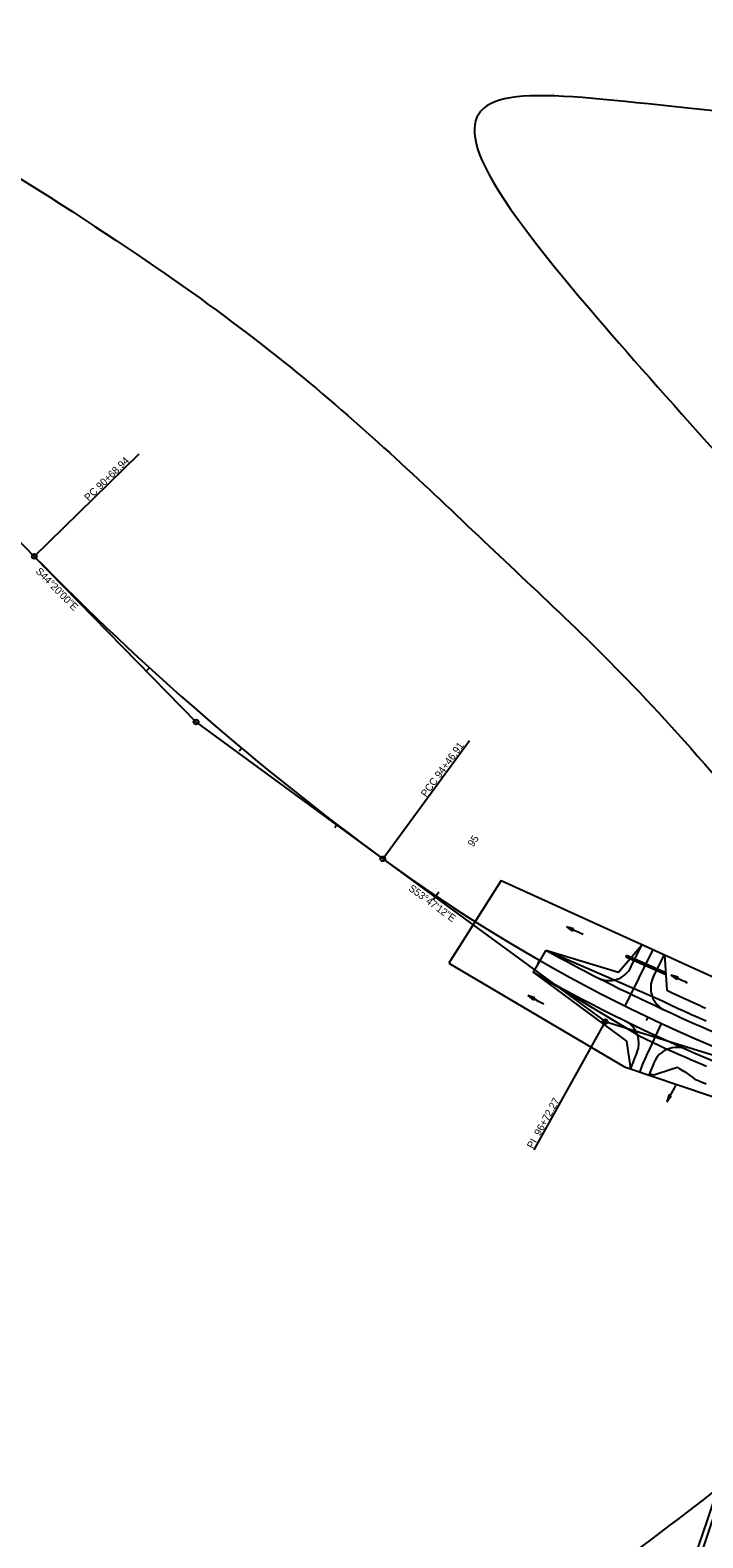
# Model space of a CAD drawing. Extents: x 1 to 1477871, y 1 to 1872901.
# Drawn here: x 1442950 to 1443501, y 1854698 to 1855932 of the extents above; entities that cross this region are included whole.
import ezdxf

# ---------------------------------------------------------------- set-up
doc = ezdxf.new("R2010")
doc.units = 0
for name, color, linetype in [('R_Drive', 7, 'Continuous'), ('R_Floodplain', 7, 'Continuous'), ('R_Horz Alg', 7, 'Continuous'), ('R_Horz Alg Annot', 7, 'Continuous'), ('R_No Plot', 7, 'Continuous'), ('R_Proposed Const Limits_Cut', 7, 'Continuous'), ('R_Proposed Const Limits_Fill', 7, 'Continuous'), ('R_Proposed Road_Lane', 7, 'Continuous'), ('R_Proposed Road_Shoulder', 7, 'Continuous'), ('R_ROW', 7, 'Continuous'), ('R_Water', 7, 'Continuous')]:
    doc.layers.add(name, color=color, linetype=linetype)

msp = doc.modelspace()

# ---------------------------------------------------------------- linework, layer by layer
at = {"layer": 'R_Drive'}
for p, q in [((1443441.9, 1855165.4), (1443451, 1855183.7)), ((1443451, 1855183.7), (1443469.2, 1855175.4)), ((1443460.1, 1855157.1), (1443469.2, 1855175.4)), ((1443441.5, 1855082), (1443456.7, 1855076.9))]:
    msp.add_line(p, q, dxfattribs=at)
for centre, radius, start, end in [((1443424, 1855174.3), 20, 243.049, 333.6597), ((1443478, 1855148.2), 20, 153.6597, 244.9648), ((1443428.4, 1855103.2), 20, 336.3358, 63.8895), ((1443637.2, 1855011.7), 208, 156.3358, 160.2285), ((1443479.2, 1855079.6), 20, 66.2169, 156.7535), ((1443637.2, 1855011.7), 192, 156.7535, 160.1367)]:
    msp.add_arc(centre, radius, start, end, dxfattribs=at)
at = {"layer": 'R_Floodplain'}
for points in [[(1444534.2, 1857777.8), (1444398.8, 1857609.1), (1444367.9, 1857131.5), (1444306.1, 1856808.3), (1444135, 1856378.3), (1444024.6, 1856227.9), (1443837.9, 1855964.8), (1443664.5, 1855852.1), (1443479, 1855867.8), (1443336, 1855886), (1443298.4, 1855854.5), (1443356.6, 1855756.3), (1443606.5, 1855482.3), (1443757.2, 1855307.3), (1443863.1, 1855113.6), (1443878.6, 1855007.9), (1443849.9, 1854910.1), (1443760.7, 1854753.1), (1443429.3, 1854512), (1443240.9, 1854371.2), (1443115.3, 1854254), (1443060.9, 1853889.1), (1443100, 1853680.3), (1443032.1, 1853386.7), (1443001.5, 1853198.3), (1444534.2, 1857777.8), (1443001.5, 1853198.3)], [(1442151.1, 1856970.7), (1442271.2, 1856854.3), (1442333, 1856625.2), (1442433.6, 1856208.1), (1442553.7, 1856042), (1442997.4, 1855782.6), (1443193.8, 1855637.1), (1443334.5, 1855500.1), (1443473.9, 1855372.8), (1443683.7, 1855109.7), (1443730.1, 1855020.6), (1443721.3, 1854972.2), (1443705.7, 1854932.6), (1443621.8, 1854821.7), (1443387.2, 1854639.6), (1443131.3, 1854479.5), (1443010.1, 1854397.1), (1442954.3, 1854286.7), (1442894.9, 1853873.3), (1442881.6, 1853521.7), (1442881.6, 1853348.3), (1442151.1, 1856970.7), (1442881.6, 1853348.3)]]:
    msp.add_open_spline(points, degree=3, dxfattribs=at)
at = {"layer": 'R_Horz Alg'}
msp.add_line((1442739.1, 1855720.9), (1442953.7, 1855501.3), dxfattribs=at)
for centre, radius, start, end in [((1444592.3, 1857102.2), 2290.8, 224.3333, 233.7866), ((1444035.4, 1856341.6), 1348.1, 233.7866, 252.7667), ((1444035.4, 1856341.6), 1348.1, 233.7866, 252.7667)]:
    msp.add_arc(centre, radius, start, end, dxfattribs=at)
at = {"layer": 'R_Horz Alg Annot'}
for p, q in [((1442953.7, 1855501.3), (1443086.1, 1855365.8)), ((1443086.1, 1855365.8), (1443238.9, 1855253.9)), ((1443238.9, 1855253.9), (1443420.7, 1855120.7)), ((1443238.9, 1855253.9), (1443420.7, 1855120.7)), ((1443420.7, 1855120.7), (1443636, 1855054))]:
    msp.add_line(p, q, dxfattribs=at)
for points in [[(1442953.7, 1855501.3), (1443039.6, 1855585.1)], [(1443045.9, 1855408), (1443047.9, 1855410.2)], [(1443238.9, 1855253.9), (1443309.8, 1855350.7)], [(1443121.3, 1855342.1), (1443123.2, 1855344.4)], [(1443199.5, 1855279.6), (1443201.3, 1855282)], [(1443284.6, 1855226.7), (1443280.1, 1855220)], [(1443365.8, 1855168), (1443367.3, 1855170.6)], [(1443420.7, 1855120.7), (1443362.5, 1855015.8)], [(1443454.6, 1855121.6), (1443455.9, 1855124.3)]]:
    msp.add_lwpolyline(points, dxfattribs=at)
for centre in [(1442953.7, 1855501.3), (1443086.1, 1855365.8), (1443238.9, 1855253.9), (1443420.7, 1855120.7)]:
    msp.add_circle(centre, 2, dxfattribs=at)
at = {"layer": 'R_No Plot'}
for p, q in [((1443372.2, 1855179.1), (1443361.8, 1855161.1)), ((1443437.2, 1855133.4), (1443460.1, 1855179.6)), ((1443466.7, 1855119.2), (1443455.9, 1855096))]:
    msp.add_line(p, q, dxfattribs=at)
msp.add_arc((1443637.2, 1855011.7), 200, 155.0504, 160.1844, dxfattribs=at)
at = {"layer": 'R_Proposed Const Limits_Cut'}
for points in [[(1443372.2, 1855179.1), (1443431.6, 1855161.3), (1443451, 1855183.7), (1443469.2, 1855175.4), (1443471.1, 1855146.4)], [(1443361.8, 1855161.1), (1443438.2, 1855104.6), (1443441.5, 1855082), (1443456.7, 1855076.9), (1443458.6, 1855077.6), (1443460.6, 1855077.3), (1443475.5, 1855082.2), (1443478.2, 1855082.9), (1443479.6, 1855083.5)]]:
    msp.add_lwpolyline(points, dxfattribs=at)
at = {"layer": 'R_Proposed Const Limits_Fill'}
for points in [[(1443471.1, 1855146.4), (1443471.8, 1855146.2), (1443473.9, 1855145.1), (1443476.1, 1855144), (1443480.5, 1855142.1), (1443480.6, 1855142), (1443485.1, 1855140), (1443487.1, 1855139), (1443489.5, 1855137.9), (1443493.7, 1855136), (1443494, 1855135.8), (1443498.4, 1855133.8), (1443500.4, 1855132.9), (1443502.9, 1855131.8)], [(1443479.6, 1855083.5), (1443481.2, 1855082.4), (1443485.3, 1855080), (1443485.6, 1855079.8), (1443489.8, 1855076.8), (1443491.6, 1855075.5), (1443494.1, 1855073.7), (1443498.3, 1855071.9), (1443498.8, 1855071.7), (1443503.5, 1855069.8)]]:
    msp.add_lwpolyline(points, dxfattribs=at)
at = {"layer": 'R_Proposed Road_Lane'}
for centre, radius, start, end in [((1444020.9, 1856348.4), 1337.1, 240.9749, 245.227), ((1444035.4, 1856341.6), 1359.1, 240.293, 252.7667), ((1444035.4, 1856341.6), 1337.1, 244.5429, 252.7667)]:
    msp.add_arc(centre, radius, start, end, dxfattribs=at)
at = {"layer": 'R_Proposed Road_Shoulder'}
for p, q in [((1443372.2, 1855179.1), (1443463.2, 1855139.7)), ((1443448.6, 1855109), (1443361.8, 1855161.1))]:
    msp.add_line(p, q, dxfattribs=at)
for points in [[(1443463.2, 1855139.7), (1443467.7, 1855137.6), (1443469.8, 1855136.5), (1443472.1, 1855135.5), (1443476.5, 1855133.4), (1443476.6, 1855133.4), (1443481.1, 1855131.3), (1443483.2, 1855130.4), (1443485.6, 1855129.3), (1443489.9, 1855127.3), (1443490.1, 1855127.2), (1443494.6, 1855125.2), (1443496.6, 1855124.4), (1443499.1, 1855123.2), (1443503.3, 1855121.4)], [(1443448.6, 1855109), (1443453.2, 1855106.8), (1443455.4, 1855105.8), (1443457.8, 1855104.7), (1443462.2, 1855102.6), (1443462.4, 1855102.5), (1443466.9, 1855100.4), (1443469.1, 1855099.4), (1443471.6, 1855098.3), (1443475.9, 1855096.3), (1443476.2, 1855096.2), (1443480.8, 1855094.2), (1443482.8, 1855093.3), (1443485.4, 1855092.1), (1443489.7, 1855090.2), (1443490.1, 1855090.1), (1443494.7, 1855088.1), (1443496.6, 1855087.2), (1443499.4, 1855086.1), (1443503.6, 1855084.3)]]:
    msp.add_lwpolyline(points, dxfattribs=at)
at = {"layer": 'R_ROW'}
for p, q in [((1443335.8, 1855236.2), (1443293, 1855168.6)), ((1443335.8, 1855236.2), (1443565.8, 1855131.3)), ((1443293, 1855168.6), (1443436.6, 1855083.7)), ((1443436.6, 1855083.7), (1443895.3, 1854928.7))]:
    msp.add_line(p, q, dxfattribs=at)
at = {"layer": 'R_Water'}
for p, q in [((1443389.1, 1855198.3), (1443394.1, 1855194.8)), ((1443394.9, 1855196.7), (1443389.1, 1855198.3)), ((1443394.1, 1855194.8), (1443394.9, 1855196.7)), ((1443438.2, 1855175.1), (1443437.6, 1855173.7)), ((1443438.2, 1855175.1), (1443470.5, 1855160.9)), ((1443437.6, 1855173.7), (1443469.9, 1855159.6)), ((1443469.9, 1855159.6), (1443470.5, 1855160.9)), ((1443474.5, 1855158.6), (1443479.5, 1855155.1)), ((1443480.4, 1855157.1), (1443474.5, 1855158.6)), ((1443479.5, 1855155.1), (1443480.4, 1855157.1)), ((1443357.4, 1855142.1), (1443362.1, 1855138.3)), ((1443363.1, 1855140.2), (1443357.4, 1855142.1)), ((1443362.1, 1855138.3), (1443363.1, 1855140.2)), ((1443473.1, 1855061), (1443471.1, 1855055.2)), ((1443471.1, 1855055.2), (1443474.9, 1855060)), ((1443474.9, 1855060), (1443473.1, 1855061))]:
    msp.add_line(p, q, dxfattribs=at)
for points in [[(1443402.7, 1855191.9), (1443400.4, 1855193), (1443398.7, 1855193.8), (1443395.9, 1855195.1), (1443391.3, 1855197.2), (1443389.1, 1855198.3)], [(1443488.1, 1855152.3), (1443485.9, 1855153.4), (1443484.1, 1855154.2), (1443481.3, 1855155.5), (1443476.8, 1855157.6), (1443474.5, 1855158.6)], [(1443370.6, 1855135), (1443368.3, 1855136.2), (1443366.7, 1855137), (1443364, 1855138.5), (1443359.6, 1855140.9), (1443357.4, 1855142.1)], [(1443478.3, 1855068.4), (1443477.1, 1855066.2), (1443476.2, 1855064.5), (1443474.7, 1855061.8), (1443472.3, 1855057.4), (1443471.1, 1855055.2)]]:
    msp.add_lwpolyline(points, dxfattribs=at)

# ---------------------------------------------------------------- texts
at = {"layer": 'R_Horz Alg Annot'}
for s, rotation, p in [('PC 90+68.94', 44.3333, (1442998.2, 1855546.1)), ('S44%%d20\'00"E', 314.3333, (1442954.4, 1855488.6)), ('PCC 94+46.91', 53.7866, (1443274.3, 1855303.9)), ('95', 56.043, (1443312.8, 1855263.2)), ('S53%%d47\'12"E', 323.7866, (1443259.4, 1855228.5)), ('PI  96+72.27', 60.977, (1443361.6, 1855016.3))]:
    msp.add_text(s, height=6, rotation=rotation, dxfattribs=at).set_placement(p)

doc.saveas('drawing.dxf')
